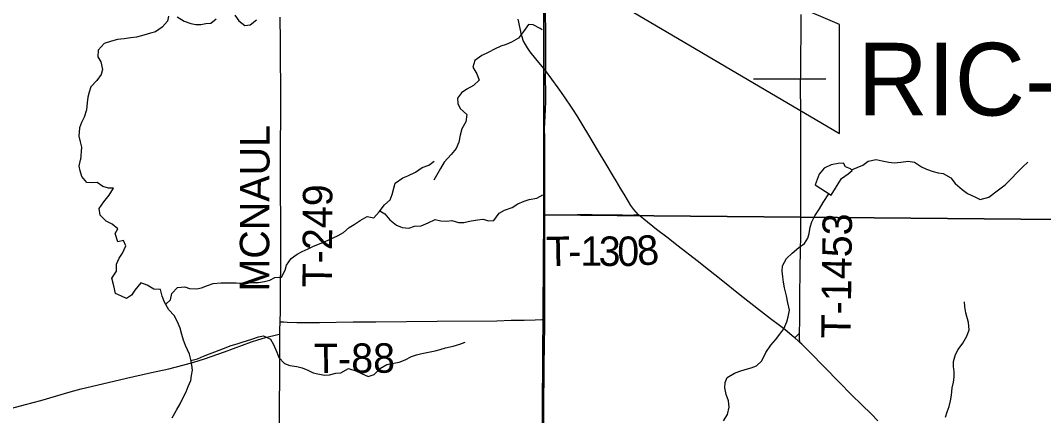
# Model space of a CAD drawing. Extents: x 0 to 70.2, y 0 to 31.4.
# Drawn here: x 5.768 to 7.741, y 15.952 to 16.713 of the extents above; entities that cross this region are included whole.
import ezdxf

# ---------------------------------------------------------------- set-up
doc = ezdxf.new("R2010")
doc.units = 0
for name, color, linetype in [('Default', 7, 'Continuous'), ('GM_X_Minor_Lake', 7, 'Continuous'), ('GM_X_Minor_River', 7, 'Continuous'), ('GM_X_Section', 7, 'Continuous'), ('GM_X_Section_Text', 7, 'Continuous'), ('GM_X_State_Route', 7, 'Continuous'), ('GM_X_Township_Road', 7, 'Continuous'), ('GM_X_Township_Road_Text', 7, 'Continuous'), ('SH_Cut_Line', 7, 'Continuous')]:
    doc.layers.add(name, color=color, linetype=linetype)

msp = doc.modelspace()

# ---------------------------------------------------------------- linework, layer by layer
at = {"layer": 'Default'}
msp.add_line((7.3217, 16.5999), (7.1817, 16.5999), dxfattribs=at)
msp.add_lwpolyline([(7.3479, 16.7052), (6.0425, 17.2633), (7.3479, 16.4952)], close=True, dxfattribs=at)
at = {"layer": 'GM_X_Minor_Lake'}
for points in [[(6.7747, 16.6952), (6.7705, 16.6981), (6.7572, 16.705), (6.7478, 16.7054), (6.7386, 16.6918), (6.729, 16.6793), (6.7153, 16.6714), (6.7051, 16.6673), (6.6948, 16.6639), (6.6823, 16.6579), (6.6701, 16.6515), (6.6579, 16.6455), (6.6446, 16.6361), (6.6408, 16.6236), (6.6483, 16.6106), (6.6528, 16.5981), (6.6421, 16.5879), (6.6292, 16.5807), (6.6189, 16.5736), (6.6109, 16.5634), (6.612, 16.5531), (6.6165, 16.5436), (6.6293, 16.5318), (6.6273, 16.5177), (6.6197, 16.5045), (6.6166, 16.4923), (6.6139, 16.4787), (6.6085, 16.4669), (6.599, 16.4548), (6.5855, 16.4406), (6.5785, 16.4278), (6.5655, 16.4055)], [(7.3317, 16.3766), (7.3518, 16.4086), (7.3645, 16.4176), (7.3719, 16.4242), (7.3688, 16.4276), (7.3596, 16.4311), (7.3556, 16.4383), (7.3454, 16.438), (7.3318, 16.435), (7.318, 16.429), (7.3088, 16.4174), (7.3009, 16.3964)], [(7.3009, 16.3964), (7.3317, 16.3766)]]:
    msp.add_lwpolyline(points, dxfattribs=at)
at = {"layer": 'GM_X_Minor_River'}
for points in [[(6.0542, 16.7214), (6.0519, 16.7119), (6.0416, 16.7002), (6.0286, 16.6915), (6.0191, 16.6885), (6.0062, 16.6848), (5.9925, 16.6814), (5.9812, 16.6796), (5.9682, 16.6781), (5.9557, 16.6767), (5.9439, 16.6733), (5.9299, 16.6692), (5.918, 16.656), (5.9176, 16.6435), (5.9233, 16.6336), (5.9266, 16.6191), (5.9243, 16.6089), (5.9155, 16.5979), (5.9044, 16.5854), (5.901, 16.5752), (5.8986, 16.5653), (5.8971, 16.5543), (5.8955, 16.5411), (5.8912, 16.5267), (5.8859, 16.5164), (5.8824, 16.5062), (5.8808, 16.4903), (5.8834, 16.4796), (5.886, 16.4694), (5.884, 16.4445)], [(6.0709, 16.7205), (6.0838, 16.7117), (6.097, 16.7075), (6.1065, 16.7055), (6.116, 16.7055), (6.1259, 16.7073), (6.1357, 16.7084), (6.146, 16.7164)], [(6.1821, 16.7234), (6.1896, 16.7127), (6.2013, 16.7039), (6.2112, 16.705), (6.2238, 16.7145)], [(5.9393, 16.377), (5.9481, 16.3903), (5.9382, 16.3903), (5.9272, 16.3937), (5.9162, 16.4009), (5.906, 16.4005), (5.8965, 16.4009), (5.887, 16.4127), (5.8836, 16.4233), (5.8817, 16.4328), (5.884, 16.4445)], [(6.0487, 16.1665), (6.0575, 16.1748), (6.0605, 16.187), (6.0715, 16.1987), (6.0852, 16.1999), (6.0947, 16.1972), (6.1083, 16.1965), (6.1178, 16.1984), (6.1292, 16.2029), (6.1402, 16.2063), (6.1546, 16.2075), (6.1644, 16.2075), (6.175, 16.2079), (6.1845, 16.2075), (6.1963, 16.2071), (6.2065, 16.2079), (6.2171, 16.2086), (6.2274, 16.2086), (6.2391, 16.2101), (6.249, 16.2128), (6.2592, 16.2181), (6.2717, 16.2189), (6.2789, 16.2321), (6.2812, 16.2416), (6.2903, 16.2549), (6.3017, 16.2629), (6.3119, 16.2682), (6.3233, 16.2735), (6.3335, 16.2784), (6.348, 16.2841), (6.3616, 16.2902), (6.3715, 16.2947), (6.3809, 16.2989), (6.3912, 16.305), (6.4026, 16.3141), (6.412, 16.3205), (6.4238, 16.3281), (6.4367, 16.3353), (6.45, 16.3331), (6.4602, 16.3448), (6.4704, 16.3581), (6.4814, 16.3676), (6.4849, 16.3782), (6.4883, 16.3903), (6.4913, 16.3998), (6.5057, 16.4101), (6.5156, 16.4142), (6.53, 16.4207), (6.5429, 16.4302), (6.5562, 16.4343), (6.5664, 16.4423)], [(7.3709, 16.4253), (7.3925, 16.4346), (7.4029, 16.442), (7.4184, 16.4454), (7.4302, 16.4427), (7.4431, 16.4403), (7.4534, 16.4391), (7.4662, 16.4401), (7.4802, 16.4424), (7.4924, 16.4404), (7.5058, 16.4316), (7.5154, 16.4269), (7.5284, 16.4223), (7.5383, 16.4198), (7.5478, 16.4185), (7.5624, 16.4102), (7.571, 16.399), (7.5842, 16.3875), (7.5949, 16.3802), (7.6087, 16.3737), (7.6191, 16.3682), (7.636, 16.3728), (7.652, 16.3853), (7.6673, 16.3963), (7.6788, 16.4084), (7.6906, 16.4204), (7.701, 16.4313), (7.711, 16.4403)], [(6.0608, 15.9476), (6.0691, 15.9624), (6.0764, 15.9746), (6.0817, 15.9856), (6.0877, 15.9981), (6.0919, 16.0083), (6.0968, 16.0197), (6.0984, 16.0292), (6.0999, 16.0394), (6.0988, 16.0489), (6.0969, 16.0603), (6.0942, 16.0702), (6.087, 16.0872), (6.0829, 16.0971), (6.0798, 16.1085), (6.0761, 16.1202), (6.0711, 16.1324), (6.0651, 16.1449), (6.0548, 16.1559), (6.0465, 16.1703), (6.0416, 16.1824), (6.0386, 16.1949), (6.0257, 16.1957), (6.0128, 16.2033), (6.0003, 16.2078), (5.9889, 16.1934), (5.9824, 16.1839), (5.9726, 16.1775), (5.9631, 16.182), (5.9517, 16.187), (5.9483, 16.2021), (5.9449, 16.2169), (5.9537, 16.2302), (5.9537, 16.2435), (5.959, 16.2556), (5.965, 16.2651), (5.9719, 16.2791), (5.9673, 16.2894), (5.9563, 16.2871), (5.951, 16.3027), (5.9564, 16.3121), (5.9454, 16.3209), (5.934, 16.3269), (5.9219, 16.3383), (5.9204, 16.3508), (5.9291, 16.3641), (5.9393, 16.377)], [(6.4615, 16.3466), (6.4708, 16.341), (6.4807, 16.3293), (6.4935, 16.319), (6.5042, 16.3145), (6.5174, 16.3133), (6.5284, 16.3171), (6.5409, 16.3175), (6.5546, 16.3232), (6.5679, 16.3297), (6.5788, 16.3274), (6.5906, 16.3266), (6.6005, 16.3281), (6.6133, 16.324), (6.6232, 16.324), (6.6376, 16.3274), (6.6501, 16.3289), (6.66, 16.3304), (6.6713, 16.327), (6.6812, 16.3278), (6.6914, 16.3418), (6.7021, 16.3475), (6.7165, 16.3532), (6.7278, 16.36), (6.7396, 16.3649), (6.7495, 16.3684), (6.7639, 16.371), (6.776, 16.3775)], [(7.1239, 15.9417), (7.1316, 15.9544), (7.135, 15.9682), (7.134, 15.9807), (7.1292, 15.9927), (7.1266, 16.0055), (7.1275, 16.0158), (7.1314, 16.0254), (7.1456, 16.0337), (7.1558, 16.0377), (7.1659, 16.0406), (7.1772, 16.0439), (7.1878, 16.0476), (7.1978, 16.0573), (7.2057, 16.0734), (7.2152, 16.0877), (7.2241, 16.0982), (7.2329, 16.109), (7.2403, 16.1194), (7.246, 16.1328), (7.2488, 16.1424), (7.2516, 16.1554), (7.2482, 16.1693), (7.2456, 16.1825), (7.2415, 16.198), (7.2397, 16.2093), (7.2383, 16.2196), (7.2373, 16.2305), (7.2378, 16.2408), (7.2455, 16.255), (7.2566, 16.2648), (7.2696, 16.2757), (7.28, 16.2835), (7.2866, 16.2936), (7.2891, 16.3031), (7.2911, 16.3149), (7.2946, 16.3256), (7.3, 16.3368), (7.3092, 16.3503), (7.3165, 16.3626), (7.3271, 16.3795)], [(7.5691, 16.0263), (7.5692, 16.0365), (7.5678, 16.0464), (7.5676, 16.0562), (7.5715, 16.0696), (7.5765, 16.0792), (7.5857, 16.0916), (7.5934, 16.105), (7.5976, 16.1173), (7.5965, 16.1317), (7.5916, 16.1498), (7.5894, 16.1615), (7.5888, 16.1713)], [(6.0972, 16.0583), (6.1101, 16.0614), (6.1215, 16.0668), (6.1329, 16.0709), (6.1435, 16.0747), (6.1602, 16.0815), (6.1746, 16.0872), (6.186, 16.0903), (6.1958, 16.0933), (6.2148, 16.0994), (6.2273, 16.1036), (6.2372, 16.1058), (6.2504, 16.099), (6.2565, 16.0888), (6.2629, 16.074), (6.2667, 16.0637), (6.2773, 16.0527), (6.2879, 16.0486), (6.3016, 16.0463), (6.3114, 16.044), (6.3228, 16.0398), (6.3327, 16.0345), (6.3421, 16.0326), (6.3546, 16.03), (6.3641, 16.0304), (6.3763, 16.0338), (6.3861, 16.0345), (6.4013, 16.0425), (6.4149, 16.0383), (6.4259, 16.033), (6.4388, 16.0273), (6.4502, 16.0315), (6.4627, 16.0433), (6.4748, 16.0505), (6.4881, 16.0531), (6.4987, 16.055), (6.5105, 16.0596), (6.5226, 16.0657), (6.5321, 16.0694), (6.5427, 16.0717), (6.5552, 16.0744), (6.5681, 16.077), (6.5776, 16.0793), (6.5882, 16.0824), (6.6026, 16.0861), (6.6159, 16.0899), (6.6257, 16.0934)], [(7.5523, 15.9492), (7.5551, 15.9595), (7.559, 15.9695), (7.5618, 15.9802), (7.5638, 15.9916), (7.565, 16.0053), (7.5674, 16.0164), (7.5691, 16.0263)]]:
    msp.add_lwpolyline(points, dxfattribs=at)
at = {"layer": 'GM_X_Section'}
for points in [[(6.7779, 17.3473), (7.7735, 17.3473), (7.7683, 16.3298), (6.7778, 16.3386)], [(6.7778, 16.3386), (7.7683, 16.3298), (7.7584, 15.3168), (6.7706, 15.321)]]:
    msp.add_lwpolyline(points, close=True, dxfattribs=at)
at = {"layer": 'GM_X_Section_Text'}
for points in [[(6.7784, 17.3526), (6.7807, 16.6175), (6.7805, 16.604), (6.7806, 16.5728), (6.7807, 16.5636), (6.7806, 16.5574), (6.7802, 16.542), (6.7795, 16.5296), (6.7787, 16.5163), (6.7784, 16.5053), (6.7788, 16.4874), (6.7789, 16.4556), (6.779, 16.4335), (6.7792, 16.4242), (6.7791, 16.4156), (6.7792, 16.4031), (6.7789, 16.3895), (6.7789, 16.3746), (6.7787, 16.3622), (6.7788, 16.339), (6.7787, 16.3156), (6.7791, 16.297), (6.7789, 16.2783), (6.7792, 16.2598), (6.7788, 16.2319), (6.7789, 16.2164), (6.7788, 16.1915), (6.7787, 16.1542), (6.7787, 16.1375), (6.7787, 16.1263), (6.7776, 16.0485), (6.7771, 15.9614), (6.7769, 15.9086)], [(6.7769, 15.9086), (6.7771, 15.9614), (6.7776, 16.0485), (6.7787, 16.1263), (6.7787, 16.1375), (6.7787, 16.1542), (6.7788, 16.1915), (6.7789, 16.2164), (6.7788, 16.2319), (6.7792, 16.2598), (6.7789, 16.2783), (6.7791, 16.297), (6.7787, 16.3156), (6.7788, 16.339), (6.7787, 16.3622), (6.7789, 16.3746), (6.7789, 16.3895), (6.7792, 16.4031), (6.7791, 16.4156), (6.7792, 16.4242), (6.779, 16.4335), (6.7789, 16.4556), (6.7788, 16.4874), (6.7784, 16.5053), (6.7787, 16.5163), (6.7795, 16.5296), (6.7802, 16.542), (6.7806, 16.5574), (6.7807, 16.5636), (6.7806, 16.5728), (6.7805, 16.604), (6.7807, 16.6175), (6.7784, 17.3526)]]:
    msp.add_lwpolyline(points, dxfattribs=at)
at = {"layer": 'GM_X_State_Route'}
for points in [[(6.7809, 16.617), (6.7748, 16.6237), (6.7649, 16.6362), (6.7572, 16.6458), (6.7535, 16.6505), (6.7502, 16.6549), (6.746, 16.6606), (6.7421, 16.6668), (6.7381, 16.6747), (6.7356, 16.6817), (6.7342, 16.6871), (6.7331, 16.6918), (6.7306, 16.7033), (6.7297, 16.7099), (6.7284, 16.7161)], [(7.4219, 15.9419), (7.4088, 15.9553), (7.3911, 15.9727), (7.3711, 15.9923), (7.347, 16.0164), (7.2903, 16.074), (7.2749, 16.0894), (7.2711, 16.093), (7.2682, 16.0958), (7.2615, 16.1017), (7.2565, 16.106), (7.2469, 16.114), (7.2396, 16.1198), (7.2322, 16.1254), (7.2148, 16.1385), (7.1976, 16.1517), (7.1561, 16.1843), (7.1196, 16.2133), (7.0953, 16.2326), (7.0734, 16.25), (7.0366, 16.2786), (7.0146, 16.2958), (6.9948, 16.3108), (6.9705, 16.3302), (6.964, 16.3357), (6.9603, 16.339), (6.9513, 16.3494), (6.9457, 16.3569), (6.9409, 16.3643), (6.9343, 16.3752), (6.9263, 16.3886), (6.917, 16.4045), (6.9122, 16.4125), (6.896, 16.4396), (6.8833, 16.4609), (6.8644, 16.4922), (6.8518, 16.5136), (6.8422, 16.5296), (6.8337, 16.5426), (6.816, 16.5682), (6.8056, 16.5837), (6.7809, 16.617)]]:
    msp.add_lwpolyline(points, dxfattribs=at)
at = {"layer": 'GM_X_Township_Road'}
for points in [[(6.2692, 16.1327), (6.2696, 16.1539), (6.2699, 16.1881), (6.2706, 16.2564), (6.2708, 16.2936), (6.2703, 16.3277), (6.2701, 16.3836), (6.2701, 16.424), (6.2701, 16.452), (6.2706, 16.5514), (6.2699, 16.6727), (6.2694, 16.7195)], [(7.2707, 16.1109), (7.271, 16.1351), (7.2714, 16.1599), (7.2716, 16.1909), (7.2721, 16.222), (7.2722, 16.2406), (7.2725, 16.2654), (7.273, 16.3027), (7.2731, 16.3275), (7.2733, 16.3772), (7.2734, 16.4207), (7.2732, 16.4952), (7.2732, 16.5387), (7.273, 16.5573), (7.2728, 16.5666), (7.2728, 16.5914), (7.273, 16.6131), (7.2732, 16.6473), (7.2736, 16.6845), (7.2739, 16.7249)], [(6.7791, 16.3384), (6.7789, 16.3616), (6.7792, 16.374), (6.7792, 16.389), (6.7794, 16.4026), (6.7793, 16.415), (6.7794, 16.4236), (6.7792, 16.4329), (6.7792, 16.455), (6.779, 16.4869), (6.7786, 16.5047), (6.7789, 16.5158), (6.7797, 16.529), (6.7804, 16.5414), (6.7808, 16.5569), (6.781, 16.563), (6.7808, 16.5723), (6.7807, 16.6034), (6.7809, 16.617)], [(6.7789, 16.1369), (6.7789, 16.1537), (6.779, 16.191), (6.7791, 16.2158), (6.779, 16.2313), (6.7795, 16.2592), (6.7792, 16.2778), (6.7794, 16.2964), (6.7789, 16.3151), (6.7791, 16.3384)], [(6.7791, 16.3384), (6.7913, 16.3386), (6.8119, 16.3388), (6.8427, 16.3396), (6.8571, 16.34), (6.871, 16.3397), (6.8922, 16.3391), (6.9077, 16.3385), (6.9296, 16.3385), (6.9418, 16.3383), (6.951, 16.3385), (6.9603, 16.339)], [(6.2689, 16.1092), (6.2689, 16.1167), (6.2692, 16.1327)], [(6.2692, 16.1327), (6.2766, 16.1324), (6.2828, 16.1321), (6.3013, 16.1315), (6.3449, 16.1315), (6.4102, 16.1325), (6.4538, 16.1326), (6.5719, 16.1338), (6.6868, 16.1349), (6.7148, 16.1357), (6.7395, 16.1361), (6.7612, 16.1366), (6.7735, 16.1369), (6.7789, 16.1369)], [(6.7771, 15.9081), (6.7773, 15.9609), (6.7778, 16.048), (6.7789, 16.1257), (6.7789, 16.1369)], [(5.7028, 15.9537), (5.778, 15.9731), (5.8079, 15.9814), (5.8645, 15.9978), (5.8854, 16.0035), (5.9154, 16.0109), (5.9728, 16.024), (6.0213, 16.0349), (6.0547, 16.0424), (6.0818, 16.0492), (6.1028, 16.055), (6.1236, 16.0617), (6.1617, 16.075), (6.2142, 16.0941), (6.2259, 16.098), (6.2408, 16.1022), (6.2648, 16.1082), (6.2689, 16.1092)], [(6.2678, 15.9332), (6.2677, 15.9661), (6.2684, 16.0323), (6.2688, 16.0949), (6.2689, 16.1092)], [(7.2615, 16.1017), (7.2648, 16.105), (7.2669, 16.1072), (7.2692, 16.1094), (7.2707, 16.1109)], [(7.2711, 16.093), (7.2709, 16.1009), (7.2707, 16.1102), (7.2707, 16.1109)]]:
    msp.add_lwpolyline(points, dxfattribs=at)
at = {"layer": 'SH_Cut_Line'}
for points in [[(6.7769, 15.9086), (6.7771, 15.9614), (6.7776, 16.0485), (6.7787, 16.1263), (6.7787, 16.1375), (6.7787, 16.1542), (6.7788, 16.1915), (6.7789, 16.2164), (6.7788, 16.2319), (6.7792, 16.2598), (6.7789, 16.2783), (6.7791, 16.297), (6.7787, 16.3156), (6.7788, 16.339), (6.7787, 16.3622), (6.7789, 16.3746), (6.7789, 16.3895), (6.7792, 16.4031), (6.7791, 16.4156), (6.7792, 16.4242), (6.779, 16.4335), (6.7789, 16.4556), (6.7788, 16.4874), (6.7784, 16.5053), (6.7787, 16.5163), (6.7795, 16.5296), (6.7802, 16.542), (6.7806, 16.5574), (6.7807, 16.5636), (6.7806, 16.5728), (6.7805, 16.604), (6.7807, 16.6175), (6.7784, 17.3526)], [(6.7784, 17.3526), (6.7807, 16.6175), (6.7805, 16.604), (6.7806, 16.5728), (6.7807, 16.5636), (6.7806, 16.5574), (6.7802, 16.542), (6.7795, 16.5296), (6.7787, 16.5163), (6.7784, 16.5053), (6.7788, 16.4874), (6.7789, 16.4556), (6.779, 16.4335), (6.7792, 16.4242), (6.7791, 16.4156), (6.7792, 16.4031), (6.7789, 16.3895), (6.7789, 16.3746), (6.7787, 16.3622), (6.7788, 16.339), (6.7787, 16.3156), (6.7791, 16.297), (6.7789, 16.2783), (6.7792, 16.2598), (6.7788, 16.2319), (6.7789, 16.2164), (6.7788, 16.1915), (6.7787, 16.1542), (6.7787, 16.1375), (6.7787, 16.1263), (6.7776, 16.0485), (6.7771, 15.9614), (6.7769, 15.9086)]]:
    msp.add_lwpolyline(points, dxfattribs=at)

# ---------------------------------------------------------------- texts
at = {"layer": 'Default'}
msp.add_text('RIC-96-16.73', height=0.14, dxfattribs=at).set_placement((7.3829, 16.5302))
at = {"layer": 'GM_X_Township_Road_Text'}
for s, height, rotation, p in [('MCNAUL', 0.05682, 89.8418, (6.248, 16.1909)), ('T-249', 0.05682, 89.7194, (6.369, 16.199)), ('T-1453', 0.05682, 89.3073, (7.3692, 16.1005)), ('T', 0.0568, 1.1743, (6.7827, 16.2396)), ('1', 0.0568, 359.9532, (6.8482, 16.2407)), ('3', 0.0568, 359.0372, (6.883, 16.2407)), ('0', 0.0568, 0.4565, (6.9195, 16.2401)), ('8', 0.0568, 5.1576, (6.9596, 16.2407)), ('-', 0.0568, 0.7572, (6.8251, 16.2404)), ('T-88', 0.05682, 0.3544, (6.3346, 16.0337))]:
    msp.add_text(s, height=height, rotation=rotation, dxfattribs=at).set_placement(p)

doc.saveas('drawing.dxf')
